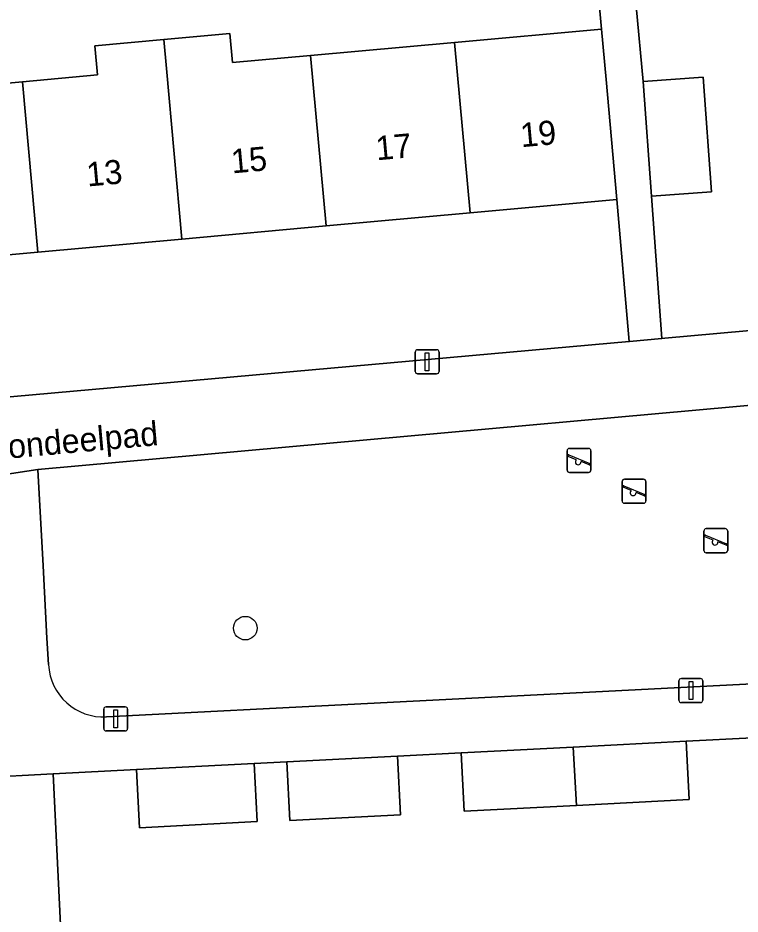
# Model space of a CAD drawing. Extents: x 160554 to 161248, y 385329 to 386506.
# Drawn here: x 160873.95 to 160903.9, y 385456.67 to 385493.85 of the extents above; entities that cross this region are included whole.
import ezdxf

# ---------------------------------------------------------------- set-up
doc = ezdxf.new("R2010")
doc.units = 0
for name, color, linetype in [('IMGEO_Boom', 7, 'Continuous'), ('IMGEO_Erf', 7, 'Continuous'), ('IMGEO_Groenvoorziening', 7, 'Continuous'), ('IMGEO_Lichtmast', 7, 'Continuous'), ('IMGEO_Openbare_ruimte_label', 7, 'Continuous'), ('IMGEO_Pand', 7, 'Continuous'), ('IMGEO_Pand_nummerreeks', 7, 'Continuous'), ('IMGEO_Speelvoorziening', 7, 'Continuous'), ('IMGEO_Voetpad_open', 7, 'Continuous')]:
    doc.layers.add(name, color=color, linetype=linetype)

msp = doc.modelspace()

# ---------------------------------------------------------------- linework, layer by layer
at = {"layer": 'IMGEO_Boom'}
msp.add_circle((160883.38, 385468.533), 0.489, dxfattribs=at)
at = {"layer": 'IMGEO_Erf'}
for points in [[(160882.741, 385493.196), (160882.851, 385491.994), (160886.085, 385492.288), (160892.06, 385492.831), (160898.156, 385493.385), (160897.322, 385502.59)], [(160899.584, 385494.338), (160899.871, 385491.211), (160902.36, 385491.394), (160902.709, 385486.637), (160900.22, 385486.454), (160900.653, 385480.551), (160900.782, 385480.563), (160922.169, 385482.49), (160920.66, 385500)], [(160868.159, 385490.659), (160874.134, 385491.202), (160877.253, 385491.486), (160877.144, 385492.688), (160880, 385492.947), (160882.741, 385493.196)], [(160844.078, 385475.481), (160899.294, 385480.429), (160898.786, 385486.308), (160892.701, 385485.757), (160886.726, 385485.216), (160880.75, 385484.674), (160874.775, 385484.133), (160868.8, 385483.592)], [(160904.409, 385463.978), (160901.665, 385463.837), (160901.789, 385461.421), (160897.111, 385461.181), (160892.455, 385460.942), (160892.331, 385463.358), (160889.692, 385463.223), (160889.817, 385460.789), (160885.229, 385460.553), (160885.104, 385462.987), (160883.751, 385462.918), (160883.875, 385460.504), (160878.988, 385460.253), (160878.864, 385462.667), (160875.415, 385462.489), (160875.971, 385451.098)]]:
    msp.add_lwpolyline(points, dxfattribs=at)
at = {"layer": 'IMGEO_Groenvoorziening'}
msp.add_lwpolyline([(160877.628, 385464.849), (160920.914, 385467.068), (160926.05, 385467.331), (160922.473, 385479.418), (160917.394, 385478.959), (160874.775, 385475.11), (160874.993, 385471.113), (160875.156, 385468.116), (160875.216, 385467.018)], dxfattribs=at)
msp.add_arc((160877.51, 385467.144), 2.298, 183.1321, 272.9407, dxfattribs=at)
at = {"layer": 'IMGEO_Lichtmast'}
for p, q in [((160890.424, 385479.184), (160890.424, 385479.984)), ((160890.424, 385479.984), (160890.424, 385479.184)), ((160890.524, 385480.084), (160891.314, 385480.084)), ((160891.314, 385480.084), (160890.524, 385480.084)), ((160891.414, 385479.984), (160891.414, 385479.184)), ((160891.414, 385479.184), (160891.414, 385479.984)), ((160891.314, 385479.084), (160890.524, 385479.084)), ((160890.524, 385479.084), (160891.314, 385479.084)), ((160901.361, 385465.542), (160901.361, 385466.342)), ((160901.361, 385466.342), (160901.361, 385465.542)), ((160901.461, 385466.442), (160902.251, 385466.442)), ((160902.251, 385466.442), (160901.461, 385466.442)), ((160902.351, 385466.342), (160902.351, 385465.542)), ((160902.351, 385465.542), (160902.351, 385466.342)), ((160877.61, 385465.268), (160878.4, 385465.268)), ((160878.4, 385465.268), (160877.61, 385465.268)), ((160902.251, 385465.442), (160901.461, 385465.442)), ((160901.461, 385465.442), (160902.251, 385465.442)), ((160877.51, 385464.368), (160877.51, 385465.168)), ((160877.51, 385465.168), (160877.51, 385464.368)), ((160878.5, 385465.168), (160878.5, 385464.368)), ((160878.5, 385464.368), (160878.5, 385465.168)), ((160878.4, 385464.268), (160877.61, 385464.268)), ((160877.61, 385464.268), (160878.4, 385464.268))]:
    msp.add_line(p, q, dxfattribs=at)
for points in [[(160890.844, 385479.959), (160890.994, 385479.959), (160890.994, 385479.209), (160890.844, 385479.209), (160890.844, 385479.959)], [(160901.781, 385466.317), (160901.931, 385466.317), (160901.931, 385465.567), (160901.781, 385465.567), (160901.781, 385466.317)], [(160877.93, 385465.143), (160878.08, 385465.143), (160878.08, 385464.393), (160877.93, 385464.393), (160877.93, 385465.143)]]:
    msp.add_lwpolyline(points, dxfattribs=at)
for centre, start, end in [((160890.524, 385479.984), 90, 180), ((160890.524, 385479.984), 90, 180), ((160891.314, 385479.984), 0, 90), ((160891.314, 385479.984), 360, 90), ((160890.524, 385479.184), 180, 270), ((160890.524, 385479.184), 180, 270), ((160891.314, 385479.184), 270, 0), ((160891.314, 385479.184), 270, 0), ((160901.461, 385466.342), 90, 180), ((160901.461, 385466.342), 90, 180), ((160902.251, 385466.342), 0, 90), ((160902.251, 385466.342), 360, 90), ((160877.61, 385465.168), 90, 180), ((160877.61, 385465.168), 90, 180), ((160878.4, 385465.168), 0, 90), ((160878.4, 385465.168), 360, 90), ((160901.461, 385465.542), 180, 270), ((160901.461, 385465.542), 180, 270), ((160902.251, 385465.542), 270, 0), ((160902.251, 385465.542), 270, 0), ((160877.61, 385464.368), 180, 270), ((160877.61, 385464.368), 180, 270), ((160878.4, 385464.368), 270, 0), ((160878.4, 385464.368), 270, 0)]:
    msp.add_arc(centre, 0.1, start, end, dxfattribs=at)
at = {"layer": 'IMGEO_Pand'}
for points in [[(160886.085, 385492.288), (160882.851, 385491.994), (160882.741, 385493.196), (160880, 385492.947), (160880.109, 385491.745), (160880.75, 385484.674), (160886.726, 385485.216)], [(160892.701, 385485.757), (160898.786, 385486.308), (160898.343, 385491.289), (160898.156, 385493.385), (160892.06, 385492.831)], [(160880, 385492.947), (160877.144, 385492.688), (160877.253, 385491.486), (160874.134, 385491.202), (160874.775, 385484.133), (160880.75, 385484.674), (160880.109, 385491.745)], [(160892.06, 385492.831), (160886.085, 385492.288), (160886.726, 385485.216), (160892.701, 385485.757)], [(160902.709, 385486.637), (160902.36, 385491.394), (160899.871, 385491.211), (160900.22, 385486.454)], [(160874.134, 385491.202), (160868.159, 385490.659), (160868.8, 385483.592), (160874.775, 385484.133)], [(160896.979, 385463.597), (160897.111, 385461.181), (160901.789, 385461.421), (160901.665, 385463.837)], [(160892.331, 385463.358), (160892.455, 385460.942), (160897.111, 385461.181), (160896.979, 385463.597)], [(160885.104, 385462.987), (160885.229, 385460.553), (160889.817, 385460.789), (160889.692, 385463.223)], [(160878.864, 385462.667), (160878.988, 385460.253), (160883.875, 385460.504), (160883.751, 385462.918)]]:
    msp.add_lwpolyline(points, close=True, dxfattribs=at)
at = {"layer": 'IMGEO_Speelvoorziening'}
for p, q in [((160896.721, 385475.091), (160896.721, 385475.891)), ((160896.721, 385475.891), (160896.721, 385475.091)), ((160897.104, 385475.519), (160896.765, 385475.656)), ((160896.79, 385475.716), (160897.666, 385475.363)), ((160896.821, 385475.991), (160897.611, 385475.991)), ((160897.611, 385475.991), (160896.821, 385475.991)), ((160897.711, 385475.891), (160897.711, 385475.091)), ((160897.711, 385475.091), (160897.711, 385475.891)), ((160897.642, 385475.303), (160897.302, 385475.44)), ((160897.611, 385474.991), (160896.821, 385474.991)), ((160896.821, 385474.991), (160897.611, 385474.991)), ((160899.001, 385473.81), (160899.001, 385474.61)), ((160899.001, 385474.61), (160899.001, 385473.81)), ((160899.101, 385474.71), (160899.891, 385474.71)), ((160899.891, 385474.71), (160899.101, 385474.71)), ((160899.991, 385474.61), (160899.991, 385473.81)), ((160899.991, 385473.81), (160899.991, 385474.61)), ((160899.384, 385474.238), (160899.045, 385474.375)), ((160899.07, 385474.435), (160899.946, 385474.082)), ((160899.922, 385474.022), (160899.582, 385474.159)), ((160899.891, 385473.71), (160899.101, 385473.71)), ((160899.101, 385473.71), (160899.891, 385473.71)), ((160902.492, 385472.659), (160903.282, 385472.659)), ((160903.282, 385472.659), (160902.492, 385472.659)), ((160902.392, 385471.759), (160902.392, 385472.559)), ((160902.392, 385472.559), (160902.392, 385471.759)), ((160902.775, 385472.187), (160902.436, 385472.324)), ((160902.461, 385472.384), (160903.337, 385472.031)), ((160903.382, 385472.559), (160903.382, 385471.759)), ((160903.382, 385471.759), (160903.382, 385472.559)), ((160903.313, 385471.971), (160902.973, 385472.108)), ((160903.282, 385471.659), (160902.492, 385471.659)), ((160902.492, 385471.659), (160903.282, 385471.659))]:
    msp.add_line(p, q, dxfattribs=at)
for centre, radius, start, end in [((160896.821, 385475.891), 0.1, 90, 180), ((160896.821, 385475.891), 0.1, 90, 180), ((160896.778, 385475.686), 0.0327, 68.078, 248.078), ((160897.611, 385475.891), 0.1, 0, 90), ((160897.611, 385475.891), 0.1, 360, 90), ((160897.183, 385475.429), 0.12, 130.9928, 5.1632), ((160897.654, 385475.333), 0.0327, 248.078, 68.078), ((160896.821, 385475.091), 0.1, 180, 270), ((160896.821, 385475.091), 0.1, 180, 270), ((160897.611, 385475.091), 0.1, 270, 0), ((160897.611, 385475.091), 0.1, 270, 0), ((160899.101, 385474.61), 0.1, 90, 180), ((160899.101, 385474.61), 0.1, 90, 180), ((160899.891, 385474.61), 0.1, 0, 90), ((160899.891, 385474.61), 0.1, 360, 90), ((160899.058, 385474.405), 0.0327, 68.078, 248.078), ((160899.463, 385474.148), 0.12, 130.9928, 5.1632), ((160899.101, 385473.81), 0.1, 180, 270), ((160899.101, 385473.81), 0.1, 180, 270), ((160899.891, 385473.81), 0.1, 270, 0), ((160899.891, 385473.81), 0.1, 270, 0), ((160899.934, 385474.052), 0.0327, 248.078, 68.078), ((160902.492, 385472.559), 0.1, 90, 180), ((160902.492, 385472.559), 0.1, 90, 180), ((160903.282, 385472.559), 0.1, 0, 90), ((160903.282, 385472.559), 0.1, 360, 90), ((160902.449, 385472.354), 0.0327, 68.078, 248.078), ((160902.854, 385472.097), 0.12, 130.9928, 5.1632), ((160903.325, 385472.001), 0.0327, 248.078, 68.078), ((160902.492, 385471.759), 0.1, 180, 270), ((160902.492, 385471.759), 0.1, 180, 270), ((160903.282, 385471.759), 0.1, 270, 0), ((160903.282, 385471.759), 0.1, 270, 0)]:
    msp.add_arc(centre, radius, start, end, dxfattribs=at)
at = {"layer": 'IMGEO_Voetpad_open'}
for points in [[(160897.322, 385502.59), (160898.156, 385493.385), (160898.343, 385491.289), (160898.786, 385486.308), (160899.294, 385480.429), (160899.308, 385480.43), (160900.653, 385480.551), (160900.22, 385486.454), (160899.871, 385491.211), (160899.584, 385494.338)], [(160935.852, 385483.721), (160931.149, 385483.306), (160925.231, 385482.784), (160922.169, 385482.49), (160900.782, 385480.563), (160900.653, 385480.551), (160899.308, 385480.43), (160899.294, 385480.429), (160844.078, 385475.481), (160835.652, 385474.705), (160836.409, 385471.526), (160857.008, 385473.35), (160871.661, 385474.647), (160874.775, 385475.11), (160917.394, 385478.959), (160922.473, 385479.418), (160927.044, 385479.479)], [(161073.558, 385475.649), (161059.018, 385474.939), (161039.256, 385473.975), (161034.076, 385473.696), (161021.904, 385472.987), (161006.397, 385472.211), (161000.588, 385471.974), (161000, 385471.944), (160988.554, 385471.363), (160987.92, 385471.331), (160951.932, 385469.506), (160926.05, 385467.331), (160920.914, 385467.068), (160877.628, 385464.849)], [(160875.216, 385467.018), (160875.156, 385468.116), (160874.993, 385471.113), (160874.775, 385475.11), (160871.661, 385474.647), (160871.994, 385468.436), (160872.321, 385462.323), (160875.415, 385462.489), (160878.864, 385462.667), (160883.751, 385462.918), (160885.104, 385462.987), (160889.692, 385463.223), (160892.331, 385463.358), (160896.979, 385463.597), (160901.665, 385463.837), (160904.409, 385463.978), (160908.998, 385464.214), (160913.696, 385464.455), (160916.331, 385464.591), (160921.103, 385464.835), (160926.084, 385465.091), (160929.105, 385465.306), (160950.644, 385466.407)], [(160877.831, 385441.882), (160877.149, 385444.331), (160876.68, 385446.013), (160876.223, 385448.541), (160875.971, 385451.098), (160875.415, 385462.489), (160872.321, 385462.323), (160872.804, 385453.308), (160872.807, 385453.283), (160873.18, 385446.657), (160873.745, 385444.568), (160875.528, 385444.927), (160875.786, 385444.037), (160876.959, 385438.645), (160876.752, 385437.199), (160877.729, 385437.253), (160897.243, 385438.326)]]:
    msp.add_lwpolyline(points, dxfattribs=at)
msp.add_arc((160877.51, 385467.144), 2.298, 183.1321, 272.9407, dxfattribs=at)

# ---------------------------------------------------------------- texts
at = {"layer": 'IMGEO_Openbare_ruimte_label'}
msp.add_text('Blondeelpad', height=1, rotation=5.1633, dxfattribs=at).set_placement((160872.399, 385475.458))
at = {"layer": 'IMGEO_Pand_nummerreeks'}
for s, rotation, p in [('19', 5.1756, (160894.828, 385488.481)), ('17', 5.1756, (160888.831, 385487.937)), ('15', 5.1738, (160882.834, 385487.394)), ('13', 5.1738, (160876.837, 385486.851))]:
    msp.add_text(s, height=1, rotation=rotation, dxfattribs=at).set_placement(p)

doc.saveas('drawing.dxf')
